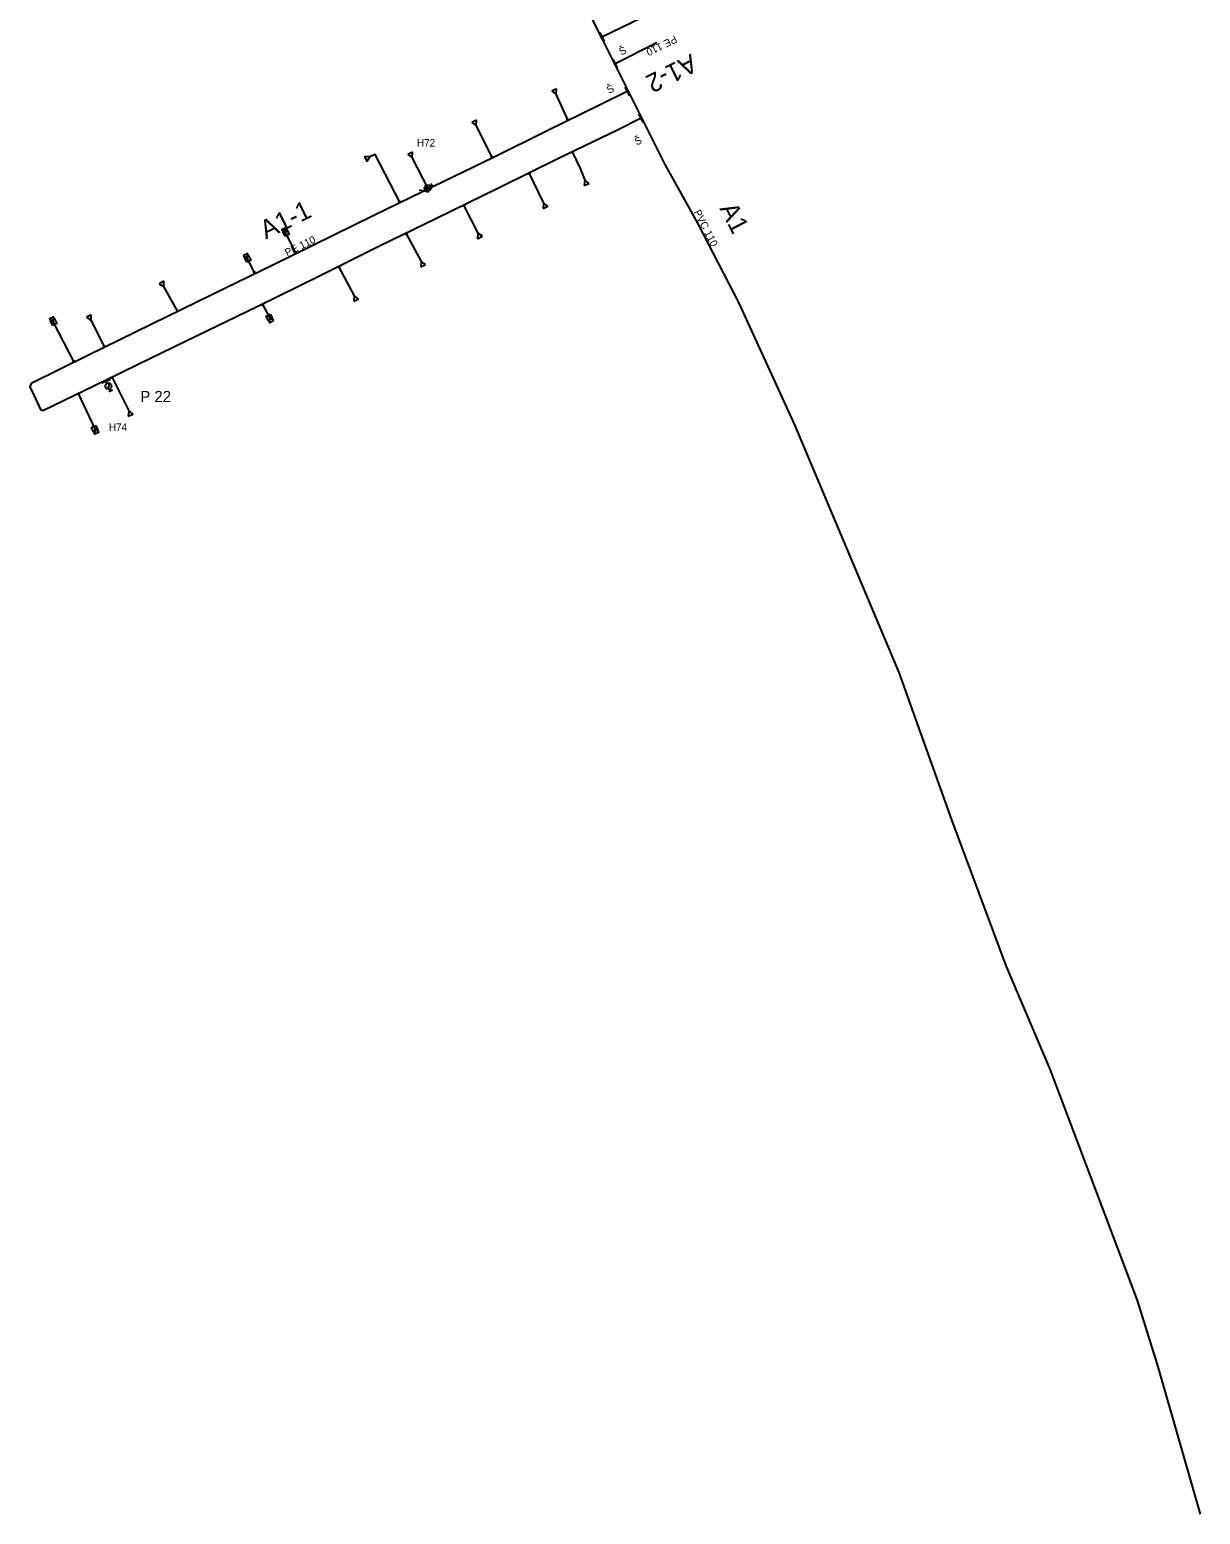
# Model space of a CAD drawing. Extents: x -574467 to -573664, y -1191210 to -1190404.
# Drawn here: x -573979 to -573664.3, y -1191209.6 to -1190810.5 of the extents above; entities that cross this region are included whole.
import ezdxf

# ---------------------------------------------------------------- set-up
doc = ezdxf.new("R2010")
doc.units = 0
for name, color, linetype in [('Vrstva 1', 7, 'Continuous'), ('Vrstva 12', 7, 'Continuous'), ('Vrstva 15', 7, 'Continuous'), ('Vrstva 25', 7, 'Continuous'), ('Vrstva 28', 7, 'Continuous'), ('Vrstva 29', 7, 'Continuous'), ('Vrstva 35', 7, 'Continuous')]:
    doc.layers.add(name, color=color, linetype=linetype)

# ---------------------------------------------------------------- blocks, each defined once
blk = doc.blocks.new('160')
at = {"layer": 'Vrstva 1'}
blk.add_circle((0, 0), 0.0458, dxfattribs=at)
blk = doc.blocks.new('147')
at = {"layer": 'Vrstva 1'}
blk.add_line((0, 1.27), (0, -1.27), dxfattribs=at)
blk = doc.blocks.new('133')
at = {"layer": 'Vrstva 1'}
for p, q in [((0.28, 0), (0, 0)), ((0.54, 0.58), (1.7, -0.58)), ((1.94, 0), (2.52, 0)), ((2.52, 0.58), (2.52, -0.58))]:
    blk.add_line(p, q, dxfattribs=at)
blk.add_circle((1.105, 0.003), 0.825, dxfattribs=at)
blk = doc.blocks.new('150')
at = {"layer": 'Vrstva 1'}
blk.add_line((0, 1.27), (0, -1.27), dxfattribs=at)
blk = doc.blocks.new('151')
at = {"layer": 'Vrstva 1'}
blk.add_line((0, 0.4), (0, -0.4), dxfattribs=at)
blk = doc.blocks.new('130')
at = {"layer": 'Vrstva 1'}
for p, q in [((1.25, 0.72), (0, 0)), ((0, 0), (1.25, -0.72)), ((1.25, -0.72), (1.25, 0.72))]:
    blk.add_line(p, q, dxfattribs=at)
blk = doc.blocks.new('171')
at = {"layer": 'Vrstva 1'}
blk.add_lwpolyline([(-0.68, 0.61), (0.67, 0.61), (0.67, -0.62), (-0.68, -0.62), (-0.68, 0.61)], dxfattribs=at)

msp = doc.modelspace()

# ---------------------------------------------------------------- linework, layer by layer
at = {"layer": 'Vrstva 12'}
for p, q in [((-573834.277, -1190834.934), (-573837.505, -1190827.834)), ((-573854.642, -1190844.963), (-573858.961, -1190836.266)), ((-573871.849, -1190853.352), (-573876.18, -1190844.826)), ((-573844.82, -1190848.975), (-573840.885, -1190857.102)), ((-573862.383, -1190857.626), (-573858.509, -1190865.235)), ((-573907.407, -1190870.727), (-573910.115, -1190865.149)), ((-573877.853, -1190865.202), (-573873.799, -1190872.832)), ((-573918.414, -1190876.106), (-573920.436, -1190872.087)), ((-573895.992, -1190874.112), (-573891.789, -1190882.069)), ((-573939.164, -1190886.238), (-573942.972, -1190879.552)), ((-573916.519, -1190884.22), (-573914.572, -1190887.827)), ((-573967.072, -1190899.895), (-573972.592, -1190889.128)), ((-573958.829, -1190895.861), (-573962.52, -1190888.566)), ((-573956.912, -1190903.847), (-573952.387, -1190912.989)), ((-573966.008, -1190908.266), (-573961.535, -1190917.766))]:
    msp.add_line(p, q, dxfattribs=at)
for points in [[(-573833.173, -1190843.287), (-573831.033, -1190847.769), (-573829.775, -1190850.917)], [(-573879.452, -1190857.052), (-573886.167, -1190844.009), (-573887.579, -1190844.698)]]:
    msp.add_lwpolyline(points, dxfattribs=at)
at = {"layer": 'Vrstva 15'}
for p, q in [((-573825.19, -1190812.42), (-573814.47, -1190807.24)), ((-573825.422, -1190812.532), (-573825.19, -1190812.42)), ((-573825.422, -1190812.532), (-573821.811, -1190819.687)), ((-573821.66, -1190819.61), (-573810.64, -1190814.02)), ((-573821.811, -1190819.687), (-573821.66, -1190819.61)), ((-573821.811, -1190819.687), (-573818.13, -1190826.98)), ((-573818.13, -1190826.98), (-573818.4, -1190827.1)), ((-573818.13, -1190826.98), (-573814.51, -1190834.2)), ((-573814.78, -1190834.31), (-573814.51, -1190834.2))]:
    msp.add_line(p, q, dxfattribs=at)
for points in [[(-573867.128, -1190729.122), (-573861.589, -1190739.127), (-573851.202, -1190758.85), (-573837.67, -1190786.28), (-573827.129, -1190809.15), (-573825.422, -1190812.532)], [(-573818.4, -1190827.1), (-573825.5, -1190830.6), (-573840.04, -1190837.78), (-573854.35, -1190844.82), (-573873.2, -1190854.01), (-573886.64, -1190860.55), (-573897.47, -1190865.85), (-573913.65, -1190873.79), (-573929.9, -1190881.69), (-573946.36, -1190889.77), (-573963.35, -1190898.07), (-573978.65, -1190905.57), (-573979.01, -1190906.47), (-573977.84, -1190908.91), (-573976.09, -1190912.62), (-573975.46, -1190912.84), (-573958.6, -1190904.68), (-573949.86, -1190900.37), (-573934.14, -1190892.75), (-573917.7, -1190884.8), (-573901.26, -1190876.72), (-573884.94, -1190868.64), (-573869.79, -1190861.29), (-573852.81, -1190852.89), (-573836.83, -1190845.06), (-573820.82, -1190837.3), (-573814.78, -1190834.31)], [(-573814.51, -1190834.2), (-573808.27, -1190846.72), (-573799.468, -1190862.55), (-573788.42, -1190884.04), (-573773.444, -1190916.69), (-573745.36, -1190983.31), (-573731.25, -1191022.95), (-573716.54, -1191062.38), (-573704.78, -1191089.921), (-573681.37, -1191151.88), (-573675.92, -1191169.34), (-573664.33, -1191209.606)]]:
    msp.add_lwpolyline(points, dxfattribs=at)
at = {"layer": 'Vrstva 25'}
for points in [[(-573873.03, -1190853.91), (-573873.08, -1190853.817), (-573872.949, -1190853.724)], [(-573958.6, -1190904.68), (-573958.46, -1190905.01), (-573958.31, -1190905.32)]]:
    msp.add_lwpolyline(points, dxfattribs=at)

# ---------------------------------------------------------------- block references
at = {"layer": 'Vrstva 12'}
for name, p, xscale, yscale, rotation in [('130', (-573837.505, -1190827.834), 0.9999999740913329, 0.9999999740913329, 114.00000060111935), ('130', (-573858.961, -1190836.266), 0.9999999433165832, 0.999999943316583, 115.9999999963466), ('151', (-573834.356, -1190834.76), 0.9999999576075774, 0.9999999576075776, -66.99999911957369), ('130', (-573876.18, -1190844.826), 0.999999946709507, 0.999999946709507, 117.00000088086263), ('151', (-573833.102, -1190843.435), 0.9999999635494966, 0.9999999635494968, -65.00000039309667), ('130', (-573887.579, -1190844.698), 1.0169561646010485, 1.0169561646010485, -153.0239835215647), ('151', (-573854.721, -1190844.805), 0.9999999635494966, 0.9999999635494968, -65.00000039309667), ('151', (-573844.728, -1190849.164), 0.9999999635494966, 0.9999999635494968, -65.00000039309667), ('130', (-573829.775, -1190850.917), 0.999999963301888, 0.9999999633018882, -69.00000101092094), ('151', (-573871.942, -1190853.169), 0.9999999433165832, 0.999999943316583, -64.0000000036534), ('151', (-573879.564, -1190856.834), 0.9999999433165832, 0.999999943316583, -64.0000000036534), ('151', (-573862.295, -1190857.799), 0.9999999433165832, 0.999999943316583, -64.0000000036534), ('130', (-573840.885, -1190857.102), 0.9999999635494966, 0.9999999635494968, -65.00000039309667), ('130', (-573910.115, -1190865.149), 0.9999999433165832, 0.999999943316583, 115.9999999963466), ('171', (-573910.115, -1190865.149), 0.9999999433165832, 0.999999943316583, 115.9999999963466), ('151', (-573877.718, -1190865.456), 0.999999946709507, 0.999999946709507, -62.999999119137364), ('130', (-573858.509, -1190865.235), 0.9999999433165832, 0.999999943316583, -64.0000000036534), ('130', (-573920.436, -1190872.087), 0.999999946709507, 0.999999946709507, 117.00000088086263), ('171', (-573920.436, -1190872.087), 0.999999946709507, 0.999999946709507, 117.00000088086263), ('151', (-573907.5, -1190870.536), 0.9999999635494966, 0.9999999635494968, -65.00000039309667), ('151', (-573895.922, -1190874.243), 0.999999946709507, 0.999999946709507, -62.999999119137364), ('130', (-573873.799, -1190872.832), 0.999999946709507, 0.999999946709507, -62.999999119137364), ('130', (-573942.972, -1190879.552), 0.9999999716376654, 0.9999999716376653, 119.99999896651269), ('151', (-573918.537, -1190875.862), 0.9999999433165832, 0.999999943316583, -64.0000000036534), ('130', (-573891.789, -1190882.069), 0.999999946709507, 0.999999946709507, -62.999999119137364), ('130', (-573962.52, -1190888.566), 0.999999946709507, 0.999999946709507, 117.00000088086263), ('151', (-573916.406, -1190884.429), 0.999999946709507, 0.999999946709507, -62.999999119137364), ('171', (-573914.572, -1190887.827), 0.999999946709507, 0.999999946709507, -62.999999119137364), ('130', (-573972.592, -1190889.128), 0.999999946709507, 0.999999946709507, 117.00000088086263), ('171', (-573972.592, -1190889.128), 0.999999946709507, 0.999999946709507, 117.00000088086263), ('130', (-573914.572, -1190887.827), 0.999999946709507, 0.999999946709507, -62.999999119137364), ('151', (-573958.908, -1190895.705), 0.9999999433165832, 0.999999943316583, -64.0000000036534), ('151', (-573967.18, -1190899.685), 0.9999999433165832, 0.999999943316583, -64.0000000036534), ('151', (-573956.823, -1190904.027), 0.9999999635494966, 0.9999999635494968, -65.00000039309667), ('151', (-573965.926, -1190908.44), 0.9999999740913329, 0.9999999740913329, -65.99999939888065), ('130', (-573952.387, -1190912.989), 0.9999999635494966, 0.9999999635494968, -65.00000039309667), ('171', (-573961.535, -1190917.766), 0.9999999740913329, 0.9999999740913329, -65.99999939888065), ('130', (-573961.535, -1190917.766), 0.9999999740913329, 0.9999999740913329, -65.99999939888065)]:
    msp.add_blockref(name, p, dxfattribs=dict(at, xscale=xscale, yscale=yscale, rotation=rotation))
at = {"layer": 'Vrstva 25'}
for name, p, xscale, yscale, rotation in [('150', (-573873.08, -1190853.817), 0.9999999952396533, 0.9999999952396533, 77.00000056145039), ('133', (-573872.949, -1190853.724), 0.9999999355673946, 0.9999999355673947, 34.99999939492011), ('150', (-573958.46, -1190905.01), 0.9999999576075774, 0.9999999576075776, -66.99999911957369), ('133', (-573958.31, -1190905.32), 0.9999999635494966, 0.9999999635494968, -65.00000039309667)]:
    msp.add_blockref(name, p, dxfattribs=dict(at, xscale=xscale, yscale=yscale, rotation=rotation))
at = {"layer": 'Vrstva 29'}
for name, p, xscale, yscale, rotation in [('147', (-573825.19, -1190812.42), 1.0138864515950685, 1.0138864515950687, 27.5653151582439), ('160', (-573825.422, -1190812.532), 0.9999999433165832, 0.999999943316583, -64.0000000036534), ('160', (-573810.64, -1190814.02), 1.0106517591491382, 1.010651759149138, 28.162115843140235), ('147', (-573821.66, -1190819.61), 1.0106517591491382, 1.010651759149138, 28.162115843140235), ('160', (-573821.811, -1190819.687), 0.9999999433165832, 0.999999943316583, -64.0000000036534), ('147', (-573818.4, -1190827.1), 1.0169561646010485, 1.0169561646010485, 26.97601647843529), ('160', (-573818.13, -1190826.98), 0.9999999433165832, 0.999999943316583, -64.0000000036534), ('147', (-573814.78, -1190834.31), 1.0198568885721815, 1.0198568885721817, 26.39398240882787), ('160', (-573814.51, -1190834.2), 0.9999999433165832, 0.999999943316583, -64.0000000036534)]:
    msp.add_blockref(name, p, dxfattribs=dict(at, xscale=xscale, yscale=yscale, rotation=rotation))

# ---------------------------------------------------------------- texts
at = {"layer": 'Vrstva 25'}
for s, height, p in [('H72', 2, (-573874.929, -1190841.904)), ('P 22', 3, (-573949.27, -1190910.61)), ('H74', 2, (-573957.74, -1190918.36))]:
    msp.add_text(s, height=height, dxfattribs=at).set_placement(p)
at = {"layer": 'Vrstva 28'}
for rotation, p in [(27.4, (-573819.954, -1190817.454)), (25.6, (-573823.302, -1190827.749)), (24.75, (-573815.867, -1190841.646))]:
    msp.add_text('Š', height=2, rotation=rotation, dxfattribs=at).set_placement(p)
at = {"layer": 'Vrstva 35'}
for s, height, rotation, p in [('PE 110', 2, 206.34, (-573805.624, -1190811.98)), ('A1-2', 5, 206.52, (-573801.207, -1190816.879)), ('A1-1', 5, 26.14, (-573915.532, -1190866.914)), ('PVC 110', 2, 297.21, (-573800.579, -1190859.512)), ('A1', 5, 297.21, (-573793.649, -1190858.553)), ('PE 110', 2, 26.14, (-573909.813, -1190871.461)), ('PE 110', 2, 26.14, (-573909.813, -1190871.461))]:
    msp.add_text(s, height=height, rotation=rotation, dxfattribs=at).set_placement(p)

doc.saveas('drawing.dxf')
